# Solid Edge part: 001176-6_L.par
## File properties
Last saved by: morva
Revision: 82
Accuracy: 0.990
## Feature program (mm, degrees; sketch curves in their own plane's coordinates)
body "unnamed Body 1"
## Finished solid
Body 1: solid body, 10 faces, 24 edges, 12 vertices.
  Faces by surface: torus 8, spline 2
  Edges by curve: circle 18, curve on surface 4, spline 2
Bounding box of the edges (mm; curved faces can reach further): 5.500 x 5.500 x 8.500, from (-2.75, -2.75, -0.25) to (2.75, 2.75, 8.25).
Toroidal faces (ring radius, tube radius in mm): R2.5 r0.25 x8
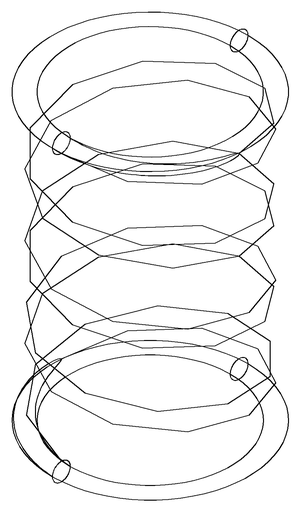
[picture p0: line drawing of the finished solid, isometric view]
